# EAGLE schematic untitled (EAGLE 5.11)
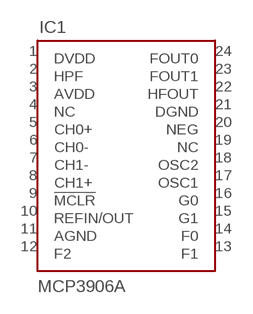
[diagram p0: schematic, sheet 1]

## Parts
IC1  MCP3906A  [SSOP-24]
Unconnected: IC1.1(DVDD) IC1.2(HPF) IC1.3(AVDD) IC1.4(NC) IC1.5(CH0+) IC1.6(CH0-) IC1.7(CH1-) IC1.8(CH1+) IC1.9(!MCLR) IC1.10(REFIN/OUT) IC1.11(AGND) IC1.12(F2) IC1.13(F1) IC1.14(F0) IC1.15(G1) IC1.16(G0) IC1.17(OSC1) IC1.18(OSC2) IC1.19(NC) IC1.20(NEG) IC1.21(DGND) IC1.22(HFOUT) IC1.23(FOUT1) IC1.24(FOUT0)

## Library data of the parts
IC1 = trl:MCP3906A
